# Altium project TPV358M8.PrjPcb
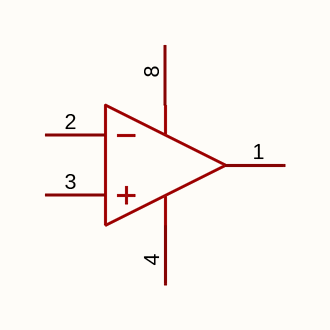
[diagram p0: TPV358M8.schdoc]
1 sheet, 1 parts. Net scope: global (net labels, ports and power ports of the same name join across sheets).

## Sheet TPV358M8.schdoc
size 127 x 101 mm

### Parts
U?  tpv358m8  [MSOP-8_L3.0-W3.0-P0.65-LS5.0-BL]  (value not drawn)  (part A of 2)

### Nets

Not connected (* = marked no-connect by the designer): U? 1(OUTA) 2(INA-) 3(INA+) 4(VSS) 8(VDD)

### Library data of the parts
U? = tpv358m8: 放大器数:2;轨到轨:轨到轨输入,轨到轨输出;增益带宽积(GBW):1MHz;输入失调电压(Vos):5mV;压摆率(SR):600V/ms;输入偏置电流(Ib):10pA;; Manufacturer: TECH PUBLIC(台舟); AddInBom: yes; ModelId: 1de5a054e9244f539c6db8238d445f94; ModelTransform: 118.11,196.85,0,0,0,0,0,0,0; Number of Channels: 2; Maximum Power Supply Range (Vdd-Vss): 7V; Gain Bandwidth Product: 1MHz; Vos - Input Offset Voltage: 5mV; Input Offset Voltage Drift(Vos TC): 2uV/℃; Ib - Input Bias Current: 10pA; Input Voltage Noise Density: 20nV/√Hz@10kHz; Common Mode Rejection Ratio(CMRR): 80dB; Quiescent Current: 40uA; Output Current: 20mA; Single supply: 2.2V~5.5V; Dual Supply: 1.1V~2.75V；-2.75V~-1.1V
